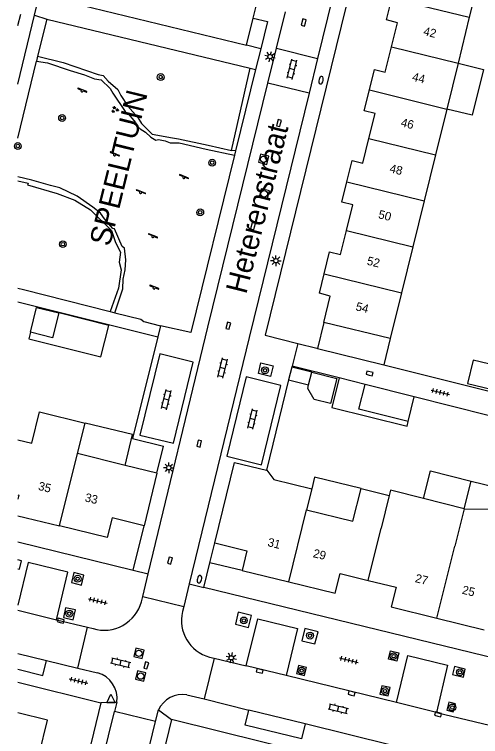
# Model space of a CAD drawing. Extents: x 128000 to 131008, y 398996 to 402500.
# Drawn here: x 127999.6 to 128054.3, y 399356.7 to 399441.3 of the extents above; entities that cross this region are included whole.
import ezdxf

# ---------------------------------------------------------------- set-up
doc = ezdxf.new("R2010")
doc.units = 0
for name, color, linetype in [('gg-afsc-erfafscheiding', 7, 'Continuous'), ('gg-afsc-hekwerk', 7, 'Continuous'), ('gg-afsc-muur', 7, 'Continuous'), ('gg-anno-huisnummerreeks BGT', 7, 'Continuous'), ('gg-anno-openbare ruimte label', 7, 'Continuous'), ('gg-bbg-gedigitaliseerde bebouwing', 7, 'Continuous'), ('gg-bbg-gedigitaliseerde bijgebouw', 7, 'Continuous'), ('gg-bbg-hoofdgebouw', 7, 'Continuous'), ('gg-bbg-luifel en loopbrug', 7, 'Continuous'), ('gg-bbg-tussenscheiding', 7, 'Continuous'), ('gg-knt-verharding', 7, 'Continuous'), ('gg-knt-verharding nz', 7, 'Continuous'), ('gt-afsc-boombescherming', 7, 'Continuous'), ('gt-anno-overige text', 7, 'Continuous'), ('gt-grn-groengrens', 7, 'Continuous'), ('gt-grn-weggrens', 7, 'Continuous'), ('gt-symb-boom', 7, 'Continuous'), ('gt-symb-brandkraan', 7, 'Continuous'), ('gt-symb-groenvak', 7, 'Continuous'), ('gt-symb-klinker verharding', 7, 'Continuous'), ('gt-symb-kolk', 7, 'Continuous'), ('gt-symb-lichtmast', 7, 'Continuous'), ('gt-symb-rioolschacht', 7, 'Continuous'), ('gt-symb-speelvoorziening', 7, 'Continuous'), ('gt-symb-tegel verharding', 7, 'Continuous'), ('gt-symb-waterafsluiter', 7, 'Continuous')]:
    doc.layers.add(name, color=color, linetype=linetype)

# ---------------------------------------------------------------- blocks, each defined once
blk = doc.blocks.new('gt0-SV')
at = {"layer": 'gt-symb-speelvoorziening'}
for p, q in [((-0.477, 0.255), (-0.08, 0.096)), ((0.542, -0.076), (-0.449, 0.324)), ((0.125, 0.014), (0.515, -0.143))]:
    blk.add_line(p, q, dxfattribs=at)
for centre, radius, start, end in [((-0.466, 0.291), 0.0369, 63.6251, 252.66016), ((-0.002, -0.005), 0.128, 127.68665, 8.59861), ((0.531, -0.111), 0.0363, 243.50852, 72.54358)]:
    blk.add_arc(centre, radius, start, end, dxfattribs=at)
blk = doc.blocks.new('gt0-BOOM')
at = {"layer": 'gt-symb-boom'}
for radius in [0.4, 0.2]:
    blk.add_circle((0, 0), radius, dxfattribs=at)
blk = doc.blocks.new('gt0-TEG1')
at = {"layer": 'gt-symb-tegel verharding'}
for p, q in [((-1.125, 0), (1.125, 0)), ((-0.9, -0.25), (-0.9, 0.25)), ((-0.45, -0.25), (-0.45, 0.25)), ((0, -0.25), (0, 0.25)), ((0.45, -0.25), (0.45, 0.25)), ((0.9, -0.25), (0.9, 0.25))]:
    blk.add_line(p, q, dxfattribs=at)
blk = doc.blocks.new('gt0-KOLK')
at = {"layer": 'gt-symb-kolk'}
blk.add_lwpolyline([(0, 0), (0.375, 0), (0.375, 0.4), (-0.375, 0.4), (-0.375, 0), (0, 0)], dxfattribs=at)
blk = doc.blocks.new('gt0-RS')
at = {"layer": 'gt-symb-rioolschacht'}
blk.add_lwpolyline([(-0.5, -0.5), (0.5, -0.5), (0.5, 0.5), (-0.5, 0.5)], close=True, dxfattribs=at)
blk.add_circle((0, 0), 0.375, dxfattribs=at)
blk = doc.blocks.new('gt0-BR')
at = {"layer": 'gt-symb-brandkraan'}
for centre, radius, start, end in [((-0.244, 0), 0.206, 107.56694, 252.43307), ((0.599, -2.664), 3, 106.89205, 107.56694), ((0, -0.691), 0.938, 73.10799, 106.89205), ((-0.599, -2.664), 3, 72.43309, 73.10799), ((0.244, 0), 0.206, 287.56695, 72.43309), ((0.599, 2.664), 3, 252.43307, 253.10797), ((0, 0.691), 0.938, 253.10797, 286.89206), ((-0.599, 2.664), 3, 286.89206, 287.56695)]:
    blk.add_arc(centre, radius, start, end, dxfattribs=at)
blk = doc.blocks.new('gt0-KL1')
at = {"layer": 'gt-symb-klinker verharding'}
for p, q in [((-1.15, 0.3), (1.15, 0.3)), ((-1, -0.3), (-1, 0.3)), ((-0.5, 0.3), (-0.5, 0.45)), ((0, -0.3), (0, 0.3)), ((0.5, 0.3), (0.5, 0.45)), ((1, -0.3), (1, 0.3)), ((-1.15, -0.3), (1.15, -0.3)), ((-0.5, -0.45), (-0.5, -0.3)), ((0.5, -0.45), (0.5, -0.3))]:
    blk.add_line(p, q, dxfattribs=at)
blk = doc.blocks.new('gt0-LMAST')
at = {"layer": 'gt-symb-lichtmast'}
for p, q in [((-0.182, 0.173), (-0.447, 0.438)), ((-0.005, 0.246), (-0.005, 0.621)), ((0.172, 0.173), (0.437, 0.438)), ((-0.255, -0.004), (-0.63, -0.004)), ((-0.182, -0.181), (-0.447, -0.446)), ((-0.005, -0.254), (-0.005, -0.629)), ((0.437, -0.446), (0.172, -0.181)), ((0.245, -0.004), (0.62, -0.004))]:
    blk.add_line(p, q, dxfattribs=at)
blk.add_circle((-0.005, -0.004), 0.25, dxfattribs=at)
blk = doc.blocks.new('gt0-GRVAK')
at = {"layer": 'gt-symb-groenvak'}
for p, q in [((-0.11, 0.189), (-0.228, 0.24)), ((-0.182, 0.153), (0.088, 0.153)), ((-0.091, 0.211), (-0.156, 0.322)), ((-0.047, 0.214), (-0.047, 0.393)), ((-0.004, 0.211), (0.061, 0.322)), ((0.015, 0.189), (0.133, 0.24)), ((0.262, -0.052), (0.197, 0.059)), ((0.305, -0.049), (0.305, 0.13)), ((0.349, -0.052), (0.414, 0.059)), ((-0.245, -0.228), (-0.363, -0.177)), ((-0.318, -0.264), (-0.047, -0.264)), ((-0.226, -0.206), (-0.291, -0.095)), ((-0.183, -0.203), (-0.183, -0.024)), ((-0.139, -0.206), (-0.074, -0.095)), ((-0.12, -0.228), (-0.002, -0.177)), ((0.243, -0.074), (0.125, -0.023)), ((0.17, -0.11), (0.441, -0.11)), ((0.368, -0.074), (0.486, -0.023))]:
    blk.add_line(p, q, dxfattribs=at)
blk = doc.blocks.new('gt0-WAFSL')
at = {"layer": 'gt-symb-waterafsluiter'}
for p, q in [((-0.5, -0.333), (0, 0.667)), ((0, 0.667), (0.5, -0.333)), ((0.5, -0.333), (-0.5, -0.333))]:
    blk.add_line(p, q, dxfattribs=at)

msp = doc.modelspace()

# ---------------------------------------------------------------- linework, layer by layer
at = {"layer": 'gg-afsc-erfafscheiding'}
msp.add_line((128035.042, 399402.235), (128035.133, 399402.212), dxfattribs=at)
msp.add_lwpolyline([(128042.915, 399400.269), (128055.727, 399397.069), (128057.124, 399402.662)], dxfattribs=at)
at = {"layer": 'gg-afsc-hekwerk'}
for p, q in [((128001.967, 399441.245), (128002.542, 399443.609)), ((128007.47, 399442.41), (128026.82, 399437.72)), ((128000, 399433.164), (128001.967, 399441.245)), ((128028.48, 399437.311), (128026.82, 399437.72)), ((128028.48, 399437.311), (128027.883, 399434.883)), ((128027.883, 399434.883), (128025.54, 399425.36)), ((128025.54, 399425.36), (128025.414, 399424.845)), ((128016.726, 399404.864), (128016.401, 399403.554))]:
    msp.add_line(p, q, dxfattribs=at)
msp.add_lwpolyline([(128025.414, 399424.845), (128020.301, 399404.063), (128016.726, 399404.864)], dxfattribs=at)
at = {"layer": 'gg-afsc-muur'}
for p, q in [((128000, 399407.652), (128016.401, 399403.554)), ((128032.149, 399400.128), (128032.123, 399400.022)), ((128037.66, 399398.74), (128032.149, 399400.128)), ((128031.752, 399398.512), (128029.153, 399387.945)), ((128055.13, 399394.34), (128046.479, 399396.519)), ((128016.3, 399387.57), (128017.073, 399390.746))]:
    msp.add_line(p, q, dxfattribs=at)
msp.add_lwpolyline([(128016.401, 399403.554), (128013.445, 399391.647), (128017.073, 399390.746)], dxfattribs=at)
at = {"layer": 'gg-bbg-gedigitaliseerde bebouwing'}
for p, q in [((128054.25, 399446.39), (128052.93, 399441.02)), ((128052.93, 399441.02), (128051.607, 399435.639)), ((128051.607, 399435.639), (128050.284, 399430.257)), ((128050.284, 399430.257), (128048.961, 399424.876)), ((128048.961, 399424.876), (128047.638, 399419.493)), ((128047.638, 399419.493), (128046.315, 399414.111)), ((128046.315, 399414.111), (128044.992, 399408.73)), ((128044.992, 399408.73), (128043.67, 399403.35)), ((128007.001, 399389.88), (128007.889, 399393.467)), ((128000, 399391.509), (128001.634, 399391.111)), ((128012.585, 399388.493), (128007.001, 399389.88)), ((128016.3, 399387.57), (128012.585, 399388.493)), ((128034.47, 399385.772), (128033.84, 399383.295)), ((128040.239, 399385.794), (128043.52, 399384.971)), ((128052.342, 399383.422), (128047.55, 399384.625)), ((128052.342, 399383.422), (128061.629, 399383.273))]:
    msp.add_line(p, q, dxfattribs=at)
for points in [[(128001.634, 399391.111), (128002.527, 399394.773), (128007.889, 399393.467)], [(128029.153, 399387.945), (128029.192, 399387.936), (128030.005, 399386.864), (128034.47, 399385.772)], [(128033.84, 399383.295), (128039.296, 399381.961), (128040.239, 399385.794)], [(128047.55, 399384.625), (128043.677, 399385.597), (128043.52, 399384.971)]]:
    msp.add_lwpolyline(points, dxfattribs=at)
at = {"layer": 'gg-bbg-gedigitaliseerde bijgebouw'}
for p, q in [((128000, 399440.024), (128000.341, 399441.385)), ((128034.091, 399397.923), (128034.471, 399399.431)), ((128046.479, 399396.519), (128040.706, 399397.973)), ((128045.774, 399393.651), (128046.479, 399396.519))]:
    msp.add_line(p, q, dxfattribs=at)
for points in [[(128001.472, 399404.104), (128002.208, 399407.017), (128004.796, 399406.364)], [(128004.796, 399406.364), (128004.061, 399403.451), (128001.472, 399404.104)], [(128052.734, 399398.086), (128055.491, 399397.418), (128056.159, 399400.174), (128053.402, 399400.843), (128052.734, 399398.086)], [(128034.471, 399399.431), (128037.414, 399398.69), (128036.673, 399395.746), (128034.733, 399396.234), (128033.982, 399397.491), (128034.091, 399397.923)], [(128045.774, 399393.651), (128039.993, 399395.072), (128040.706, 399397.973)]]:
    msp.add_lwpolyline(points, dxfattribs=at)
at = {"layer": 'gg-bbg-hoofdgebouw'}
for p, q in [((128043.67, 399403.35), (128035.88, 399405.26)), ((128016.3, 399387.57), (128014.81, 399381.42)), ((128000, 399382.609), (128004.903, 399381.408)), ((128026.29, 399376.17), (128031.755, 399374.84)), ((128049.122, 399370.592), (128054.69, 399369.22))]:
    msp.add_line(p, q, dxfattribs=at)
for points in [[(128043.816, 399437.551), (128044.51, 399440.37), (128043.21, 399440.69), (128043.846, 399443.25)], [(128041.212, 399432.484), (128041.8, 399434.87), (128043.08, 399434.56), (128043.816, 399437.551)], [(128041.168, 399426.788), (128041.89, 399429.73), (128040.61, 399430.04), (128041.212, 399432.484)], [(128038.566, 399421.72), (128039.181, 399424.21), (128040.46, 399423.9), (128041.168, 399426.788)], [(128038.521, 399416.024), (128039.26, 399419.03), (128037.98, 399419.35), (128038.566, 399421.72)], [(128035.922, 399410.956), (128036.55, 399413.52), (128037.83, 399413.21), (128038.521, 399416.024)], [(128035.88, 399405.26), (128036.63, 399408.34), (128035.36, 399408.66), (128035.922, 399410.956)], [(128023.11, 399379.41), (128025.402, 399388.856), (128029.153, 399387.945)], [(128000, 399385.039), (128000.12, 399385.01), (128000, 399384.528)], [(128014.81, 399381.42), (128011.05, 399382.34), (128010.49, 399380.04), (128004.903, 399381.408)], [(128023.11, 399379.41), (128026.86, 399378.5), (128026.29, 399376.17)], [(128031.755, 399374.84), (128037.22, 399373.51), (128037.79, 399375.83), (128041.077, 399375.022)], [(128041.077, 399375.022), (128044.34, 399374.22), (128043.77, 399371.91), (128049.122, 399370.592)], [(128002.491, 399354.65), (128003.48, 399358.64), (128000, 399359.5)]]:
    msp.add_lwpolyline(points, dxfattribs=at)
at = {"layer": 'gg-bbg-luifel en loopbrug'}
for p, q in [((128035.88, 399405.26), (128035.133, 399402.212)), ((128043.67, 399403.35), (128042.915, 399400.269)), ((128035.133, 399402.212), (128042.915, 399400.269)), ((128032.123, 399400.022), (128031.752, 399398.512)), ((128034.471, 399399.431), (128032.123, 399400.022)), ((128040.706, 399397.973), (128037.66, 399398.74)), ((128031.752, 399398.512), (128034.091, 399397.923)), ((128052.342, 399383.422), (128053.157, 399386.67)), ((128022.524, 399377.084), (128023.11, 399379.41)), ((128026.29, 399376.17), (128022.524, 399377.084))]:
    msp.add_line(p, q, dxfattribs=at)
for points in [[(128051.607, 399435.639), (128054.605, 399434.902), (128053.282, 399429.52), (128050.284, 399430.257)], [(128001.472, 399404.104), (128001.279, 399403.336), (128009.73, 399401.204), (128010.659, 399404.885), (128004.796, 399406.364)], [(128037.66, 399398.74), (128036.806, 399395.267), (128045.638, 399393.096), (128045.774, 399393.651)], [(128012.585, 399388.493), (128013.463, 399392.117), (128007.889, 399393.467)], [(128047.55, 399384.625), (128048.365, 399387.873), (128053.157, 399386.67)], [(128040.239, 399385.794), (128034.801, 399387.124), (128034.47, 399385.772)], [(128053.157, 399386.67), (128057.331, 399385.622), (128057.008, 399384.337), (128061.889, 399384.259), (128061.629, 399383.273)]]:
    msp.add_lwpolyline(points, dxfattribs=at)
at = {"layer": 'gg-bbg-tussenscheiding'}
for p, q in [((128043.846, 399443.25), (128052.93, 399441.02)), ((128043.816, 399437.551), (128051.607, 399435.639)), ((128041.212, 399432.484), (128050.284, 399430.257)), ((128041.168, 399426.788), (128048.961, 399424.876)), ((128038.566, 399421.72), (128047.638, 399419.493)), ((128038.521, 399416.024), (128046.315, 399414.111)), ((128035.922, 399410.956), (128044.992, 399408.73)), ((128004.903, 399381.408), (128007.001, 399389.88)), ((128043.52, 399384.971), (128042.584, 399381.157)), ((128052.342, 399383.422), (128051.242, 399379.04)), ((128031.755, 399374.84), (128033.84, 399383.295)), ((128041.077, 399375.022), (128042.584, 399381.157)), ((128049.122, 399370.592), (128051.242, 399379.04))]:
    msp.add_line(p, q, dxfattribs=at)
at = {"layer": 'gg-knt-verharding'}
for p, q in [((128048.865, 399492.067), (128035.151, 399436.183)), ((128027.604, 399440.918), (128027.969, 399442.48)), ((128026.82, 399437.72), (128027.604, 399440.918)), ((128030.331, 399437.399), (128031.37, 399441.625)), ((128029.315, 399433.266), (128030.331, 399437.399)), ((128030.331, 399437.399), (128035.151, 399436.183)), ((128035.151, 399436.183), (128034.148, 399432.098)), ((128034.148, 399432.098), (128029.315, 399433.266)), ((128032.814, 399402.791), (128035.042, 399402.235)), ((128013.532, 399376.239), (128014.81, 399381.42)), ((128000, 399379.547), (128013.532, 399376.239)), ((128021.8, 399374.21), (128022.524, 399377.084)), ((128014.648, 399373.138), (128015.294, 399375.805)), ((128020.099, 399374.628), (128019.449, 399371.96)), ((128075.23, 399361.16), (128021.8, 399374.21)), ((128014.501, 399372.531), (128014.648, 399373.138)), ((128014.648, 399373.138), (128019.449, 399371.96)), ((128019.449, 399371.96), (128019.304, 399371.365)), ((128004.522, 399370.418), (128008.179, 399369.534)), ((128007.034, 399364.757), (128008.179, 399369.534)), ((128008.179, 399369.534), (128008.82, 399369.379)), ((128003.355, 399365.64), (128007.034, 399364.757)), ((128023.02, 399365.907), (128021.83, 399361.132)), ((128022.471, 399366.038), (128023.02, 399365.907)), ((128023.02, 399365.907), (128026.769, 399365.015)), ((128007.034, 399364.757), (128009.331, 399364.205)), ((128000, 399363.088), (128009.749, 399360.698)), ((128044.385, 399360.715), (128031.451, 399363.872)), ((128019.82, 399361.625), (128021.83, 399361.132)), ((128009.749, 399360.698), (128007.95, 399353.3)), ((128011.605, 399360.766), (128011.333, 399359.666)), ((128021.83, 399361.132), (128027.096, 399359.839)), ((128016.16, 399358.488), (128016.49, 399359.843)), ((128016.16, 399358.488), (128011.333, 399359.666)), ((128049.104, 399359.563), (128059.241, 399357.089)), ((128018, 399358.72), (128016.144, 399351.084)), ((128075.07, 399344.66), (128018, 399358.72)), ((128043.919, 399355.694), (128033.694, 399358.214))]:
    msp.add_line(p, q, dxfattribs=at)
for points in [[(128040.294, 399449.707), (128028.995, 399403.745), (128032.814, 399402.791)], [(128027.604, 399440.918), (128029.27, 399440.52), (128028.48, 399437.311)], [(128015.294, 399375.805), (128022.29, 399404.68), (128029.315, 399433.266)], [(128034.148, 399432.098), (128027.13, 399403.5), (128020.099, 399374.628)], [(128014.319, 399392.044), (128018.251, 399391.098), (128020.559, 399400.599), (128016.642, 399401.577), (128014.319, 399392.044)], [(128029.925, 399400.18), (128029.617, 399398.915), (128028.219, 399399.26), (128028.496, 399400.507), (128029.925, 399400.18)], [(128024.505, 399389.576), (128028.554, 399388.564), (128030.841, 399397.864), (128026.767, 399398.876), (128024.505, 399389.576)], [(128000, 399376.384), (128000.183, 399376.337), (128000.421, 399377.329), (128000, 399377.437)], [(128004.522, 399370.418), (128005.857, 399375.988), (128001.211, 399377.127), (128000, 399372.141)], [(128006.58, 399375.943), (128006.301, 399374.768), (128007.479, 399374.479), (128007.755, 399375.65), (128006.58, 399375.943)], [(128005.601, 399371.827), (128005.346, 399370.669), (128006.505, 399370.4), (128006.782, 399371.567), (128005.601, 399371.827)], [(128027.033, 399369.513), (128027.384, 399370.901), (128025.834, 399371.303), (128025.506, 399369.901), (128027.033, 399369.513)], [(128026.769, 399365.015), (128028.132, 399370.536), (128032.782, 399369.388), (128031.451, 399363.872)], [(128033.305, 399367.96), (128034.835, 399367.604), (128035.2, 399368.982), (128033.636, 399369.379), (128033.305, 399367.96)], [(128043.441, 399365.792), (128043.684, 399366.772), (128044.661, 399366.524), (128044.418, 399365.544), (128043.441, 399365.792)], [(128000, 399364.611), (128002.918, 399363.894), (128003.355, 399365.64)], [(128044.385, 399360.715), (128045.738, 399366.23), (128050.386, 399365.09), (128049.104, 399359.563)], [(128033.627, 399363.879), (128033.842, 399364.837), (128032.898, 399365.049), (128032.67, 399364.103), (128033.627, 399363.879)], [(128052.457, 399364.626), (128051.186, 399364.936), (128050.963, 399363.981), (128052.234, 399363.671), (128052.457, 399364.626)], [(128042.444, 399361.714), (128043.421, 399361.499), (128043.642, 399362.466), (128042.668, 399362.682), (128042.444, 399361.714)], [(128051.298, 399360.566), (128050.548, 399360.745), (128050.314, 399359.813), (128051.054, 399359.61), (128051.298, 399360.566)], [(128033.694, 399358.214), (128033.247, 399356.45), (128026.665, 399358.062), (128027.096, 399359.839)], [(128000, 399321.019), (128003.53, 399335.46), (128005.66, 399336.69), (128011.333, 399359.666)], [(128008.1, 399318.179), (128011.86, 399333.37), (128010.57, 399335.52), (128016.16, 399358.488)]]:
    msp.add_lwpolyline(points, dxfattribs=at)
for centre, radius, start, end in [((128010.128, 399373.717), 4.531, 253.22293, 344.82289), ((128023.641, 399370.338), 4.457, 166.6829, 254.78163), ((128008.527, 399361.202), 3.108, 351.93279, 75.01565), ((128019.341, 399358.518), 3.144, 81.23476, 155.07085)]:
    msp.add_arc(centre, radius, start, end, dxfattribs=at)
at = {"layer": 'gg-knt-verharding nz'}
for p, q in [((128000, 399371.531), (128004.522, 399370.418)), ((128000, 399366.461), (128003.355, 399365.64)), ((128031.451, 399363.872), (128026.769, 399365.015)), ((128049.104, 399359.563), (128044.385, 399360.715)), ((128033.694, 399358.214), (128027.096, 399359.839))]:
    msp.add_line(p, q, dxfattribs=at)
at = {"layer": 'gt-afsc-boombescherming'}
for points in [[(128002.194, 399435.878), (128003.496, 399435.654), (128006.138, 399434.782), (128007.812, 399434.247), (128008.992, 399433.778), (128009.772, 399433.69), (128010.845, 399432.668), (128011.146, 399432.108), (128012.574, 399429.981), (128012.992, 399429.659), (128013.786, 399428.689), (128013.994, 399428.252), (128014.329, 399427.928), (128014.96, 399427.56), (128015.593, 399426.964), (128016.198, 399426.611), (128016.507, 399426.694), (128017.291, 399426.533), (128017.869, 399426.312), (128018.928, 399426.312), (128022.087, 399425.561), (128025.414, 399424.845)], [(128002.328, 399436.431), (128005.299, 399435.719), (128009.425, 399434.292), (128010.019, 399434.17), (128010.576, 399433.52), (128011.731, 399432.549), (128012.06, 399431.831), (128012.907, 399430.57), (128014.084, 399429.256), (128014.501, 399428.554), (128015.739, 399427.31), (128018.123, 399426.869), (128018.839, 399426.777), (128022.332, 399426.031), (128025.036, 399425.411)], [(128011.377, 399406.391), (128012.3, 399409.191), (128012.357, 399410.334), (128012.601, 399411.423), (128012.647, 399412.567), (128012.527, 399413.947), (128012.227, 399414.166), (128011.35, 399416.236), (128011.155, 399416.256), (128010.159, 399417.375), (128009.698, 399418.059), (128008.808, 399418.755), (128006.968, 399420.055), (128004.922, 399421.007), (128003.832, 399421.293), (128001.654, 399421.913), (128000, 399422.326)], [(128000, 399421.857), (128001.2, 399421.551), (128001.155, 399421.373), (128004.599, 399420.359), (128006.667, 399419.586), (128008.537, 399418.424), (128010.966, 399416.04), (128011.458, 399414.622), (128012.025, 399413.492), (128011.875, 399412.298), (128012.106, 399411.412), (128011.823, 399409.252), (128010.828, 399406.53)]]:
    msp.add_lwpolyline(points, dxfattribs=at)
at = {"layer": 'gt-grn-groengrens'}
for p, q in [((128001.967, 399441.245), (128003.389, 399440.798)), ((128003.389, 399440.798), (128002.328, 399436.431)), ((128003.389, 399440.798), (128027.232, 399435.04)), ((128000, 399426.845), (128002.194, 399435.878)), ((128002.328, 399436.431), (128002.194, 399435.878)), ((128025.036, 399425.411), (128027.232, 399435.04)), ((128027.232, 399435.04), (128027.883, 399434.883)), ((128025.54, 399425.36), (128025.036, 399425.411)), ((128010.828, 399406.53), (128011.377, 399406.391))]:
    msp.add_line(p, q, dxfattribs=at)
for points in [[(128000, 399409.266), (128000.657, 399409.113), (128010.828, 399406.53)], [(128011.377, 399406.391), (128014.424, 399405.617), (128014.769, 399405.357), (128016.726, 399404.864)]]:
    msp.add_lwpolyline(points, dxfattribs=at)
at = {"layer": 'gt-grn-weggrens'}
for p, q in [((128032.814, 399402.791), (128032.149, 399400.128)), ((128013.532, 399376.239), (128015.294, 399375.805)), ((128020.099, 399374.628), (128021.8, 399374.21)), ((128011.605, 399360.766), (128009.749, 399360.698)), ((128016.49, 399359.843), (128018, 399358.72))]:
    msp.add_line(p, q, dxfattribs=at)

# ---------------------------------------------------------------- block references
at = {"layer": 'gt-symb-boom'}
for p in [(128016.757, 399434.003), (128005.197, 399429.203), (128000.005, 399425.919), (128022.787, 399423.967), (128021.383, 399418.149), (128005.281, 399414.42), (128028.979, 399399.639), (128007.009, 399375.223), (128006.045, 399371.131), (128026.5, 399370.333), (128034.261, 399368.553), (128044.054, 399366.149), (128033.265, 399364.461), (128051.82, 399364.267), (128043.061, 399362.06), (128050.944, 399360.138)]:
    msp.add_blockref('gt0-BOOM', p, dxfattribs=at)
at = {"layer": 'gt-symb-brandkraan'}
for p, rotation in [((128035.551, 399433.639), 76.17220496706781), ((128021.295, 399375.169), 76.29711003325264)]:
    msp.add_blockref('gt0-BR', p, dxfattribs=dict(at, rotation=rotation))
at = {"layer": 'gt-symb-groenvak'}
msp.add_blockref('gt0-GRVAK', (128011.381, 399430.191), dxfattribs=at)
at = {"layer": 'gt-symb-klinker verharding'}
for p, rotation in [((128032.16, 399434.918), 76.29711003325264), ((128024.019, 399399.903), 76.28353067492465), ((128017.423, 399396.213), 76.35276166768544), ((128027.517, 399393.921), 76.3527616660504), ((128012.059, 399365.379), -13.772145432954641), ((128037.569, 399359.989), -13.716469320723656)]:
    msp.add_blockref('gt0-KL1', p, dxfattribs=dict(at, rotation=rotation))
at = {"layer": 'gt-symb-kolk'}
for p, rotation in [((128033.709, 399440.339), 73.19645198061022), ((128030.809, 399428.563), 75.46349079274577), ((128027.765, 399416.47), 74.93576605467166), ((128024.873, 399404.807), 74.10181291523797), ((128041.185, 399399.078), -14.119602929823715), ((128021.464, 399391.015), 77.17287657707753), ((128018.031, 399377.294), 76.22785456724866), ((128004.985, 399370.109), -13.772145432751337), ((128015.245, 399365.007), 73.73979529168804), ((128028.314, 399364.227), -13.827795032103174), ((128039.087, 399361.596), -13.827795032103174), ((128049.224, 399359.129), -13.827795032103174)]:
    msp.add_blockref('gt0-KOLK', p, dxfattribs=dict(at, rotation=rotation))
at = {"layer": 'gt-symb-lichtmast'}
for p, rotation in [((128029.571, 399436.402), 76.22785456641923), ((128025.025, 399365.955), -13.82779503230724)]:
    msp.add_blockref('gt0-LMAST', p, dxfattribs=dict(at, rotation=rotation))
for p in [(128030.267, 399412.482), (128017.709, 399388.223)]:
    msp.add_blockref('gt0-LMAST', p, dxfattribs=at)
at = {"layer": 'gt-symb-rioolschacht'}
for p, rotation in [((128028.823, 399424.375), 76.17220496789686), ((128028.884, 399420.316), 76.17220496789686), ((128014.199, 399366.485), -13.71646932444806), ((128014.405, 399363.811), -13.716469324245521)]:
    msp.add_blockref('gt0-RS', p, dxfattribs=dict(at, rotation=rotation))
at = {"layer": 'gt-symb-speelvoorziening'}
for p in [(128007.535, 399432.381), (128011.347, 399424.9), (128019.462, 399422.241), (128014.397, 399420.482), (128015.823, 399415.322), (128015.972, 399409.294)]:
    msp.add_blockref('gt0-SV', p, dxfattribs=at)
at = {"layer": 'gt-symb-tegel verharding'}
for p, rotation in [((128049.534, 399397.063), -13.716469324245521), ((128009.381, 399372.616), -13.71646932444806), ((128038.819, 399365.674), -13.716469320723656), ((128007.131, 399363.235), -13.71646932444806)]:
    msp.add_blockref('gt0-TEG1', p, dxfattribs=dict(at, rotation=rotation))
at = {"layer": 'gt-symb-waterafsluiter'}
msp.add_blockref('gt0-WAFSL', (128010.925, 399361.031), dxfattribs=at)

# ---------------------------------------------------------------- texts
at = {"layer": 'gg-anno-huisnummerreeks BGT'}
for s, rotation, p in [('42', 346.2, (128047.475, 399438.935)), ('44', 346.2, (128046.159, 399433.586)), ('46', 346.2, (128044.843, 399428.241)), ('48', 346.2, (128043.523, 399422.86)), ('50', 346.2, (128042.196, 399417.475)), ('52', 346.2, (128040.859, 399412.029)), ('54', 346.3, (128039.544, 399406.682)), ('35', 346.2, (128002.323, 399385.643)), ('33', 346.2, (128007.792, 399384.304)), ('31', 346.4, (128029.218, 399379.059)), ('29', 346.4, (128034.544, 399377.763)), ('27', 346.2, (128046.507, 399374.839)), ('25', 346.2, (128052.007, 399373.484))]:
    msp.add_text(s, height=1, rotation=rotation, dxfattribs=at).set_placement(p)
at = {"layer": 'gg-anno-openbare ruimte label'}
msp.add_text('Heterenstraat', height=2.5, rotation=75.8, dxfattribs=at).set_placement((128026.771, 399408.474))
at = {"layer": 'gt-anno-overige text'}
msp.add_text('SPEELTUIN', height=2.5, rotation=76.1722, dxfattribs=at).set_placement((128010.8, 399414.058))

doc.saveas('drawing.dxf')
